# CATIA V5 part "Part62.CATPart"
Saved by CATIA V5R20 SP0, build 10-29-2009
Part number: Junta
Revision: ANY
Definition: UNKNOWN
Nomenclature: Junta
Source: Unknown
Bounding box of the stored display mesh (mm): x -13.5 to 13.5, y -1.25 to 1.25, z -13.5 to 13.5
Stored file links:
  C:\Users\Utente\Desktop\IO LAVORO\3D X SITO CF\CUMSA\3D files AE\Part62.CATPart
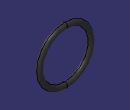
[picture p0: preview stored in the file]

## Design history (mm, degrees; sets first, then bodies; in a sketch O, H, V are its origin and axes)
Body1 "Revolución1" (main body)
  Solid1: solid without history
